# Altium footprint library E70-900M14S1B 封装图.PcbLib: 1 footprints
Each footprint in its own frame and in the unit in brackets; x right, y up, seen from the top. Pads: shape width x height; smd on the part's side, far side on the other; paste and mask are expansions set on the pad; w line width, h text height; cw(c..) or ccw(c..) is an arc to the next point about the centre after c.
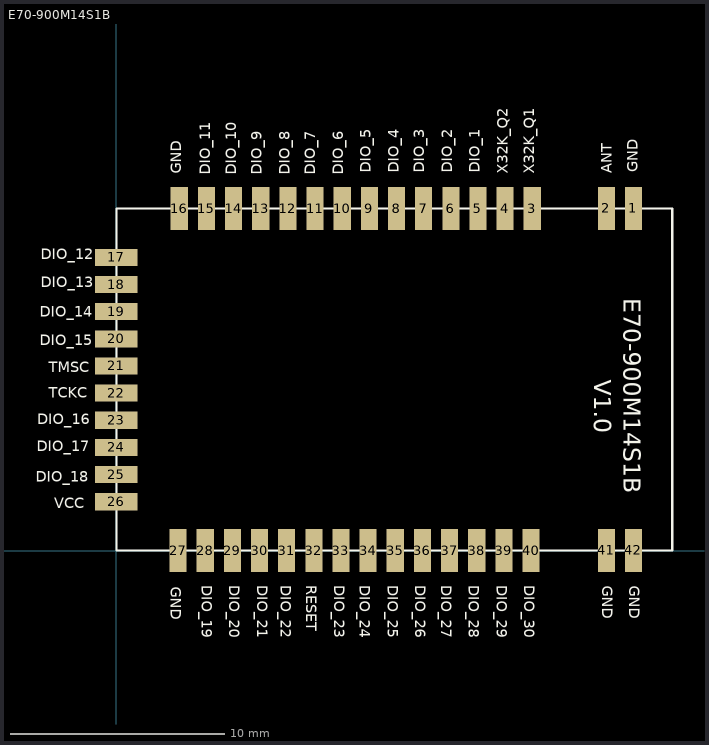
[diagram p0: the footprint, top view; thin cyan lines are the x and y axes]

## E70-900M14S1B [mm]
pads (42):
  rect 0.8x2 smd: 1(24.191,16.01) 2(22.921,16.01) 3(19.456,16.004) 4(18.186,16.004) 5(16.916,16.004) 6(15.646,16.004) 7(14.376,16.004) 8(13.106,16.004) 9(11.836,16.004) 10(10.566,16.004) 11(9.296,16.004) 12(8.026,16.004) 13(6.756,16.004) 14(5.486,16.004) 15(4.216,16.004) 16(2.946,16.004) 27(2.888,0.003) 28(4.158,0.003) 29(5.428,0.003) 30(6.698,0.003) 31(7.968,0.003) 32(9.238,0.003) 33(10.508,0.003) 34(11.778,0.003) 35(13.048,0.003) 36(14.318,0.003) 37(15.588,0.003) 38(16.858,0.003) 39(18.128,0.003) 40(19.398,0.003) 41(22.921,0.014) 42(24.191,0.014)
  rect 2x0.8 smd: 17(0.001,13.719) 18(0.001,12.449) 19(0.001,11.179) 20(0.001,9.909) 21(0.001,8.639) 22(0.001,7.369) 23(0.001,6.099) 24(0.001,4.829) 25(0.001,3.559) 26(0.001,2.289)
Top Overlay:
  lines w0.1: 0.001,0.004 26.001,0.004 26.001,16.004 0.001,16.004 0.001,0.004
  text "E70-900M14S1B" at 23.735,11.8 h0.8
  text "V1.0" at 22.352,8.001 h0.8
  text "GND" at 24.397,17.709 h0.5
  text "ANT" at 23.176,17.664 h0.5
  text "X32K_Q1" at 19.554,17.636 h0.5
  text "X32K_Q2" at 18.304,17.636 h0.5
  text "DIO_1" at 17.004,17.686 h0.5
  text "DIO_2" at 15.704,17.686 h0.5
  text "DIO_3" at 14.404,17.686 h0.5
  text "DIO_4" at 13.204,17.686 h0.5
  text "DIO_5" at 11.904,17.686 h0.5
  text "DIO_6" at 10.604,17.586 h0.5
  text "DIO_7" at 9.304,17.586 h0.5
  text "DIO_8" at 8.104,17.586 h0.5
  text "DIO_9" at 6.804,17.586 h0.5
  text "DIO_10" at 5.604,17.586 h0.5
  text "DIO_11" at 4.404,17.586 h0.5
  text "DIO_12" at -3.535,13.623 h0.5
  text "DIO_13" at -3.535,12.325 h0.5
  text "DIO_14" at -3.578,10.941 h0.5
  text "DIO_15" at -3.587,9.616 h0.5
  text "GND" at 22.725,-1.634 h0.5
  text "TMSC" at -3.165,8.35 h0.5
  text "TCKC" at -3.165,7.15 h0.5
  text "DIO_16" at -3.698,5.907 h0.5
  text "DIO_17" at -3.72,4.641 h0.5
  text "DIO_18" at -3.765,3.219 h0.5
  text "VCC" at -2.898,1.975 h0.5
  text "DIO_19" at 3.989,-1.621 h0.5
  text "DIO_20" at 5.289,-1.621 h0.5
  text "DIO_21" at 6.589,-1.621 h0.5
  text "DIO_22" at 7.689,-1.621 h0.5
  text "RESET" at 8.889,-1.621 h0.5
  text "DIO_23" at 10.189,-1.621 h0.5
  text "DIO_24" at 11.389,-1.621 h0.5
  text "DIO_25" at 12.689,-1.621 h0.5
  text "DIO_26" at 13.989,-1.621 h0.5
  text "DIO_27" at 15.189,-1.621 h0.5
  text "DIO_28" at 16.489,-1.621 h0.5
  text "DIO_29" at 17.789,-1.621 h0.5
  text "DIO_30" at 19.089,-1.621 h0.5
  text "GND" at 23.996,-1.634 h0.5
  text "GND" at 2.549,-1.681 h0.5
  text "GND" at 3.035,17.636 h0.5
